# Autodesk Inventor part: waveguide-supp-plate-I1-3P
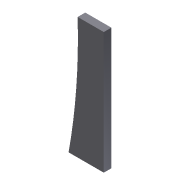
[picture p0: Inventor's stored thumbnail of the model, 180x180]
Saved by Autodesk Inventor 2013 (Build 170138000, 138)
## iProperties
Created: 2012-05
Part Number: waveguide-supp-plate-I1-3P
Material: Edelstahl
Document SubType Name: Modeling
Designer: Henneborn
Description: WAVEGUIDE SUPPORT PLATE I
Mass: 128.951 g
Surface Area: 66.5362 cm^2
Volume: 15.9593 cm^3
Density: 8.08 g/cm^3
Rohmasse: 4" x 1,18" x 0,125"
Author: vm
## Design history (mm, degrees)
sketch "Sketch1"
  geometry: L1 (0, -71.36)-(0, 71.16) reference; L2 (-605.028, 0)-(100.838, 0) reference; L3 (0, -50.8)-(0, 50.8); L4 (0, 50.8)-(-21.831, 50.8); L5 (-29.38, -50.8)-(0, -50.8); A1 r 482.6 centre (-504.19, 35.56) between (-29.38, -50.8) and (-21.831, 50.8); 1 further point
  constraints: 6 end point, 2 point on circle, 1 centre point, 1 midpoint, 1 parallel, 1 perpendicular, 1 vertical
  dimensions: "d0" = 101.6 distance of L3.start L3.end; "d7" = 965.2 diameter of A1; "d9" = 504.19 distance from line of L1 A1.centre; "d11" = 86.36 distance from line of L5 A1.centre
extrude "Extrusion1" new body sketch "Sketch1" distance "d5" = 6.35; taper "d6" = 0 deg
body "Solid1"
